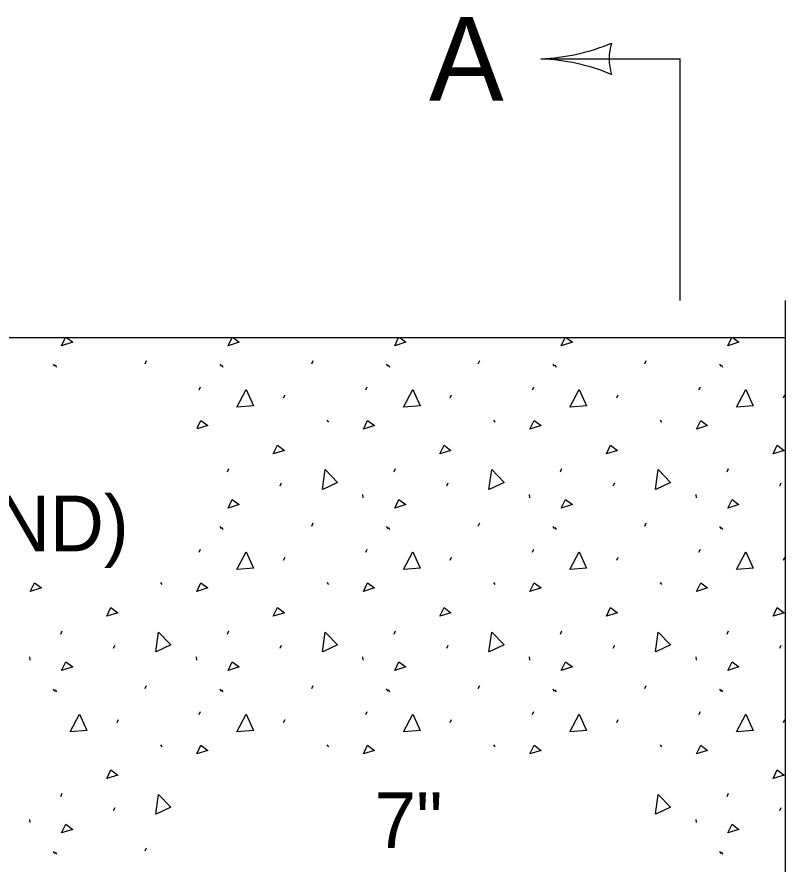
# Model space of a CAD drawing. Extents: x 49991.4 to 50021, y 49987.6 to 50011.4.
# Drawn here: x 50011.209 to 50012.035, y 49996.564 to 49997.476 of the extents above; entities that cross this region are included whole.
import ezdxf

# ---------------------------------------------------------------- set-up
doc = ezdxf.new("R2010")
doc.units = 0
for name, color, linetype in [('Level 1', 7, 'Continuous'), ('Level 2', 7, 'Continuous'), ('Level 3', 7, 'Continuous'), ('Level 6', 7, 'Continuous')]:
    doc.layers.add(name, color=color, linetype=linetype)

msp = doc.modelspace()

# ---------------------------------------------------------------- linework, layer by layer
at = {"layer": 'Level 1'}
for p, q in [((50009.70734, 49997.13065), (50012.03515, 49997.13065)), ((50011.257, 49997.12196), (50011.26117, 49997.13065)), ((50011.43616, 49997.12196), (50011.44033, 49997.13065)), ((50011.61532, 49997.12196), (50011.61949, 49997.13065)), ((50011.79448, 49997.12196), (50011.79865, 49997.13065)), ((50011.97363, 49997.12196), (50011.97781, 49997.13065)), ((50011.24792, 49997.10207), (50011.24941, 49997.09983)), ((50011.24991, 49997.10122), (50011.2514, 49997.09898)), ((50011.34689, 49997.10257), (50011.34838, 49997.10593)), ((50011.42708, 49997.10207), (50011.42857, 49997.09983)), ((50011.42907, 49997.10122), (50011.43056, 49997.09898)), ((50011.52604, 49997.10257), (50011.52754, 49997.10593)), ((50011.60623, 49997.10207), (50011.60773, 49997.09983)), ((50011.60823, 49997.10122), (50011.60972, 49997.09898)), ((50011.7052, 49997.10257), (50011.70669, 49997.10593)), ((50011.78539, 49997.10207), (50011.78689, 49997.09983)), ((50011.78739, 49997.10122), (50011.78888, 49997.09898)), ((50011.88436, 49997.10257), (50011.88585, 49997.10593)), ((50011.96455, 49997.10207), (50011.96604, 49997.09983)), ((50011.96654, 49997.10122), (50011.96804, 49997.09898)), ((50011.40507, 49997.07442), (50011.40656, 49997.07778)), ((50011.58423, 49997.07442), (50011.58572, 49997.07778)), ((50011.76339, 49997.07442), (50011.76488, 49997.07778)), ((50011.94254, 49997.07442), (50011.94404, 49997.07778)), ((50011.49583, 49997.06584), (50011.49733, 49997.0692)), ((50011.67499, 49997.06584), (50011.67648, 49997.0692)), ((50011.85415, 49997.06584), (50011.85564, 49997.0692)), ((50012.03331, 49997.06584), (50012.0348, 49997.0692)), ((50011.4029, 49997.0332), (50011.40693, 49997.0416)), ((50011.41439, 49997.03601), (50011.4029, 49997.03242)), ((50011.40693, 49997.0416), (50011.41439, 49997.03601)), ((50011.54245, 49997.04198), (50011.54395, 49997.03974)), ((50011.58162, 49997.03228), (50011.58609, 49997.0416)), ((50011.59355, 49997.03601), (50011.58162, 49997.03228)), ((50011.58609, 49997.0416), (50011.59355, 49997.03601)), ((50011.72161, 49997.04198), (50011.7231, 49997.03974)), ((50011.76077, 49997.03228), (50011.76525, 49997.0416)), ((50011.77271, 49997.03601), (50011.76077, 49997.03228)), ((50011.76525, 49997.0416), (50011.77271, 49997.03601)), ((50011.90077, 49997.04198), (50011.90226, 49997.03974)), ((50011.93993, 49997.03228), (50011.94441, 49997.0416)), ((50011.95187, 49997.03601), (50011.93993, 49997.03228)), ((50011.94441, 49997.0416), (50011.95187, 49997.03601)), ((50011.43541, 49996.9864), (50011.4369, 49996.98976)), ((50011.61457, 49996.9864), (50011.61606, 49996.98976)), ((50011.79373, 49996.9864), (50011.79522, 49996.98976)), ((50011.97289, 49996.9864), (50011.97438, 49996.98976)), ((50011.4921, 49996.97111), (50011.4936, 49996.97447)), ((50011.67126, 49996.97111), (50011.67275, 49996.97447)), ((50011.85042, 49996.97111), (50011.85191, 49996.97447)), ((50012.02958, 49996.97111), (50012.03107, 49996.97447)), ((50011.58078, 49996.96174), (50011.58115, 49996.95839)), ((50011.75994, 49996.96174), (50011.76031, 49996.95839)), ((50011.93909, 49996.96174), (50011.93947, 49996.95839)), ((50011.42708, 49996.92735), (50011.42857, 49996.92511)), ((50011.42907, 49996.9265), (50011.43056, 49996.92426)), ((50011.52604, 49996.92785), (50011.52754, 49996.9312)), ((50011.60623, 49996.92735), (50011.60773, 49996.92511)), ((50011.60823, 49996.9265), (50011.60972, 49996.92426)), ((50011.7052, 49996.92785), (50011.70669, 49996.9312)), ((50011.78539, 49996.92735), (50011.78689, 49996.92511)), ((50011.78739, 49996.9265), (50011.78888, 49996.92426)), ((50011.88436, 49996.92785), (50011.88585, 49996.9312)), ((50011.96455, 49996.92735), (50011.96604, 49996.92511)), ((50011.96654, 49996.9265), (50011.96804, 49996.92426)), ((50011.40507, 49996.8997), (50011.40656, 49996.90306)), ((50011.58423, 49996.8997), (50011.58572, 49996.90306)), ((50011.76339, 49996.8997), (50011.76488, 49996.90306)), ((50011.94254, 49996.8997), (50011.94404, 49996.90306)), ((50011.49583, 49996.89112), (50011.49733, 49996.89448)), ((50011.67499, 49996.89112), (50011.67648, 49996.89448)), ((50011.85415, 49996.89112), (50011.85564, 49996.89448)), ((50012.03331, 49996.89112), (50012.0348, 49996.89448)), ((50011.2233, 49996.85756), (50011.22777, 49996.86688)), ((50011.23523, 49996.86129), (50011.2233, 49996.85756)), ((50011.22777, 49996.86688), (50011.23523, 49996.86129)), ((50011.3633, 49996.86725), (50011.36479, 49996.86501)), ((50011.40246, 49996.85756), (50011.40693, 49996.86688)), ((50011.41439, 49996.86129), (50011.40246, 49996.85756)), ((50011.40693, 49996.86688), (50011.41439, 49996.86129)), ((50011.54245, 49996.86725), (50011.54395, 49996.86501)), ((50011.58162, 49996.85756), (50011.58609, 49996.86688)), ((50011.59355, 49996.86129), (50011.58162, 49996.85756)), ((50011.58609, 49996.86688), (50011.59355, 49996.86129)), ((50011.72161, 49996.86725), (50011.7231, 49996.86501)), ((50011.76077, 49996.85756), (50011.76525, 49996.86688)), ((50011.77271, 49996.86129), (50011.76077, 49996.85756)), ((50011.76525, 49996.86688), (50011.77271, 49996.86129)), ((50011.90077, 49996.86725), (50011.90226, 49996.86501)), ((50011.93993, 49996.85756), (50011.94441, 49996.86688)), ((50011.95187, 49996.86129), (50011.93993, 49996.85756)), ((50011.94441, 49996.86688), (50011.95187, 49996.86129)), ((50011.25625, 49996.81168), (50011.25775, 49996.81504)), ((50011.43541, 49996.81168), (50011.4369, 49996.81504)), ((50011.61457, 49996.81168), (50011.61606, 49996.81504)), ((50011.79373, 49996.81168), (50011.79522, 49996.81504)), ((50011.97289, 49996.81168), (50011.97438, 49996.81504)), ((50011.31295, 49996.79639), (50011.31444, 49996.79975)), ((50011.4921, 49996.79639), (50011.4936, 49996.79975)), ((50011.67126, 49996.79639), (50011.67275, 49996.79975)), ((50011.85042, 49996.79639), (50011.85191, 49996.79975)), ((50012.02958, 49996.79639), (50012.03107, 49996.79975)), ((50011.22246, 49996.78702), (50011.22283, 49996.78367)), ((50011.40162, 49996.78702), (50011.40199, 49996.78367)), ((50011.58078, 49996.78702), (50011.58115, 49996.78367)), ((50011.75994, 49996.78702), (50011.76031, 49996.78367)), ((50011.93909, 49996.78702), (50011.93947, 49996.78367)), ((50011.24792, 49996.75263), (50011.24941, 49996.75039)), ((50011.24991, 49996.75178), (50011.2514, 49996.74954)), ((50011.34689, 49996.75313), (50011.34838, 49996.75648)), ((50011.42708, 49996.75263), (50011.42857, 49996.75039)), ((50011.42907, 49996.75178), (50011.43056, 49996.74954)), ((50011.52604, 49996.75313), (50011.52754, 49996.75648)), ((50011.60623, 49996.75263), (50011.60773, 49996.75039)), ((50011.60823, 49996.75178), (50011.60972, 49996.74954)), ((50011.7052, 49996.75313), (50011.70669, 49996.75648)), ((50011.78539, 49996.75263), (50011.78689, 49996.75039)), ((50011.78739, 49996.75178), (50011.78888, 49996.74954)), ((50011.88436, 49996.75313), (50011.88585, 49996.75648)), ((50011.96455, 49996.75263), (50011.96604, 49996.75039)), ((50011.96654, 49996.75178), (50011.96804, 49996.74954)), ((50011.40507, 49996.72498), (50011.40656, 49996.72834)), ((50011.58423, 49996.72498), (50011.58572, 49996.72834)), ((50011.76339, 49996.72498), (50011.76488, 49996.72834)), ((50011.94254, 49996.72498), (50011.94404, 49996.72834)), ((50011.31667, 49996.7164), (50011.31817, 49996.71976)), ((50011.49583, 49996.7164), (50011.49733, 49996.71976)), ((50011.67499, 49996.7164), (50011.67648, 49996.71976)), ((50011.85415, 49996.7164), (50011.85564, 49996.71976)), ((50012.03331, 49996.7164), (50012.0348, 49996.71976)), ((50011.3633, 49996.69253), (50011.36479, 49996.69029)), ((50011.40246, 49996.68283), (50011.40693, 49996.69216)), ((50011.40693, 49996.69216), (50011.41439, 49996.68656)), ((50011.54245, 49996.69253), (50011.54395, 49996.69029)), ((50011.58162, 49996.68283), (50011.58609, 49996.69216)), ((50011.58609, 49996.69216), (50011.59355, 49996.68656)), ((50011.72161, 49996.69253), (50011.7231, 49996.69029)), ((50011.76077, 49996.68283), (50011.76525, 49996.69216)), ((50011.76525, 49996.69216), (50011.77271, 49996.68656)), ((50011.90077, 49996.69253), (50011.90226, 49996.69029)), ((50011.93993, 49996.68283), (50011.94441, 49996.69216)), ((50011.94441, 49996.69216), (50011.95187, 49996.68656)), ((50011.41439, 49996.68656), (50011.40246, 49996.68283)), ((50011.59355, 49996.68656), (50011.58162, 49996.68283)), ((50011.77271, 49996.68656), (50011.76077, 49996.68283)), ((50011.95187, 49996.68656), (50011.93993, 49996.68283)), ((50011.25625, 49996.63696), (50011.25775, 49996.64032)), ((50011.97289, 49996.63696), (50011.97438, 49996.64032)), ((50011.31295, 49996.62167), (50011.31444, 49996.62503)), ((50012.02958, 49996.62167), (50012.03107, 49996.62503)), ((50011.22246, 49996.6123), (50011.22283, 49996.60894)), ((50011.93909, 49996.6123), (50011.93947, 49996.60894)), ((50011.24792, 49996.57791), (50011.24941, 49996.57567)), ((50011.34689, 49996.57841), (50011.34838, 49996.58176)), ((50011.96455, 49996.57791), (50011.96604, 49996.57567)), ((50011.24991, 49996.57705), (50011.2514, 49996.57482)), ((50011.96654, 49996.57705), (50011.96804, 49996.57482))]:
    msp.add_line(p, q, dxfattribs=at)
for points in [[(50011.26232, 49997.13065), (50011.26894, 49997.12569), (50011.257, 49997.12196)], [(50011.44148, 49997.13065), (50011.44809, 49997.12569), (50011.43616, 49997.12196)], [(50011.62064, 49997.13065), (50011.62725, 49997.12569), (50011.61532, 49997.12196)], [(50011.7998, 49997.13065), (50011.80641, 49997.12569), (50011.79448, 49997.12196)], [(50011.97895, 49997.13065), (50011.98557, 49997.12569), (50011.97363, 49997.12196)], [(50011.44548, 49997.05578), (50011.45555, 49997.0748), (50011.46339, 49997.05727), (50011.44586, 49997.05578)], [(50011.62464, 49997.05578), (50011.63471, 49997.0748), (50011.64254, 49997.05727), (50011.62501, 49997.05578)], [(50011.8038, 49997.05578), (50011.81387, 49997.0748), (50011.8217, 49997.05727), (50011.80417, 49997.05578)], [(50011.98296, 49997.05578), (50011.99303, 49997.0748), (50012.00086, 49997.05727), (50011.98333, 49997.05578)], [(50011.48472, 49997.00562), (50011.48919, 49997.01494), (50011.49665, 49997.00935), (50011.48472, 49997.00562)], [(50011.66388, 49997.00562), (50011.66835, 49997.01494), (50011.67581, 49997.00935), (50011.66388, 49997.00562)], [(50011.84304, 49997.00562), (50011.84751, 49997.01494), (50011.85497, 49997.00935), (50011.84304, 49997.00562)], [(50012.02219, 49997.00562), (50012.02667, 49997.01494), (50012.03413, 49997.00935), (50012.02219, 49997.00562)], [(50011.53748, 49996.96725), (50011.54043, 49996.98857), (50011.55379, 49996.97478), (50011.53783, 49996.96738)], [(50011.71664, 49996.96725), (50011.71959, 49996.98857), (50011.73295, 49996.97478), (50011.71699, 49996.96738)], [(50011.8958, 49996.96725), (50011.89875, 49996.98857), (50011.91211, 49996.97478), (50011.89614, 49996.96738)], [(50011.43616, 49996.94724), (50011.44063, 49996.95657), (50011.44809, 49996.95097), (50011.43616, 49996.94724)], [(50011.61532, 49996.94724), (50011.61979, 49996.95657), (50011.62725, 49996.95097), (50011.61532, 49996.94724)], [(50011.79448, 49996.94724), (50011.79895, 49996.95657), (50011.80641, 49996.95097), (50011.79448, 49996.94724)], [(50011.97363, 49996.94724), (50011.97811, 49996.95657), (50011.98557, 49996.95097), (50011.97363, 49996.94724)], [(50011.44548, 49996.88105), (50011.45555, 49996.90007), (50011.46339, 49996.88255), (50011.44586, 49996.88105)], [(50011.62464, 49996.88105), (50011.63471, 49996.90007), (50011.64254, 49996.88255), (50011.62501, 49996.88105)], [(50011.8038, 49996.88105), (50011.81387, 49996.90007), (50011.8217, 49996.88255), (50011.80417, 49996.88105)], [(50011.98296, 49996.88105), (50011.99303, 49996.90007), (50012.00086, 49996.88255), (50011.98333, 49996.88105)], [(50011.30556, 49996.8309), (50011.31003, 49996.84022), (50011.31749, 49996.83463), (50011.30556, 49996.8309)], [(50011.48472, 49996.8309), (50011.48919, 49996.84022), (50011.49665, 49996.83463), (50011.48472, 49996.8309)], [(50011.66388, 49996.8309), (50011.66835, 49996.84022), (50011.67581, 49996.83463), (50011.66388, 49996.8309)], [(50011.84304, 49996.8309), (50011.84751, 49996.84022), (50011.85497, 49996.83463), (50011.84304, 49996.8309)], [(50012.02219, 49996.8309), (50012.02667, 49996.84022), (50012.03413, 49996.83463), (50012.02219, 49996.8309)], [(50011.35832, 49996.79253), (50011.36128, 49996.81385), (50011.37463, 49996.80006), (50011.35867, 49996.79266)], [(50011.53748, 49996.79253), (50011.54043, 49996.81385), (50011.55379, 49996.80006), (50011.53783, 49996.79266)], [(50011.71664, 49996.79253), (50011.71959, 49996.81385), (50011.73295, 49996.80006), (50011.71699, 49996.79266)], [(50011.8958, 49996.79253), (50011.89875, 49996.81385), (50011.91211, 49996.80006), (50011.89614, 49996.79266)], [(50011.257, 49996.77252), (50011.26148, 49996.78184), (50011.26894, 49996.77625), (50011.257, 49996.77252)], [(50011.43616, 49996.77252), (50011.44063, 49996.78184), (50011.44809, 49996.77625), (50011.43616, 49996.77252)], [(50011.61532, 49996.77252), (50011.61979, 49996.78184), (50011.62725, 49996.77625), (50011.61532, 49996.77252)], [(50011.79448, 49996.77252), (50011.79895, 49996.78184), (50011.80641, 49996.77625), (50011.79448, 49996.77252)], [(50011.97363, 49996.77252), (50011.97811, 49996.78184), (50011.98557, 49996.77625), (50011.97363, 49996.77252)], [(50011.26633, 49996.70633), (50011.27639, 49996.72535), (50011.28423, 49996.70783), (50011.2667, 49996.70633)], [(50011.44548, 49996.70633), (50011.45555, 49996.72535), (50011.46339, 49996.70783), (50011.44586, 49996.70633)], [(50011.62464, 49996.70633), (50011.63471, 49996.72535), (50011.64254, 49996.70783), (50011.62501, 49996.70633)], [(50011.8038, 49996.70633), (50011.81387, 49996.72535), (50011.8217, 49996.70783), (50011.80417, 49996.70633)], [(50011.98296, 49996.70633), (50011.99303, 49996.72535), (50012.00086, 49996.70783), (50011.98333, 49996.70633)], [(50011.30556, 49996.65617), (50011.31003, 49996.6655), (50011.31749, 49996.6599), (50011.30556, 49996.65617)], [(50012.02219, 49996.65617), (50012.02667, 49996.6655), (50012.03413, 49996.6599), (50012.02219, 49996.65617)], [(50011.35832, 49996.61781), (50011.36128, 49996.63913), (50011.37463, 49996.62533), (50011.35867, 49996.61794)], [(50011.8958, 49996.61781), (50011.89875, 49996.63913), (50011.91211, 49996.62533), (50011.89614, 49996.61794)], [(50011.257, 49996.5978), (50011.26148, 49996.60712), (50011.26894, 49996.60153), (50011.257, 49996.5978)], [(50011.97363, 49996.5978), (50011.97811, 49996.60712), (50011.98557, 49996.60153), (50011.97363, 49996.5978)]]:
    msp.add_lwpolyline(points, dxfattribs=at)
at = {"layer": 'Level 3'}
for p in [(50011.77247, 49997.43065), (50011.92247, 49997.17065)]:
    msp.add_line(p, (50011.92247, 49997.43065), dxfattribs=at)
for centre, radius, start, end in [((50011.76332, 49997.65279), 0.22232, 272.36048, 292.54399), ((50011.90069, 49997.43065), 0.05477, 162.13882, 197.86118), ((50011.76098, 49997.19794), 0.233, 67.92284, 87.17269)]:
    msp.add_arc(centre, radius, start, end, dxfattribs=at)
at = {"layer": 'Level 6'}
msp.add_line((50012.03515, 49997.17065), (50012.03515, 49996.31662), dxfattribs=at)

# ---------------------------------------------------------------- texts
at = {"layer": 'Level 2'}
for s, height, p in [('A', 0.09, (50011.6522, 49997.38565)), ('(SQUARE OR ROUND)', 0.06, (50010.47778, 49996.90073)), ('7" ', 0.06, (50011.5937, 49996.58142))]:
    msp.add_text(s, height=height, dxfattribs=at).set_placement(p)

doc.saveas('drawing.dxf')
